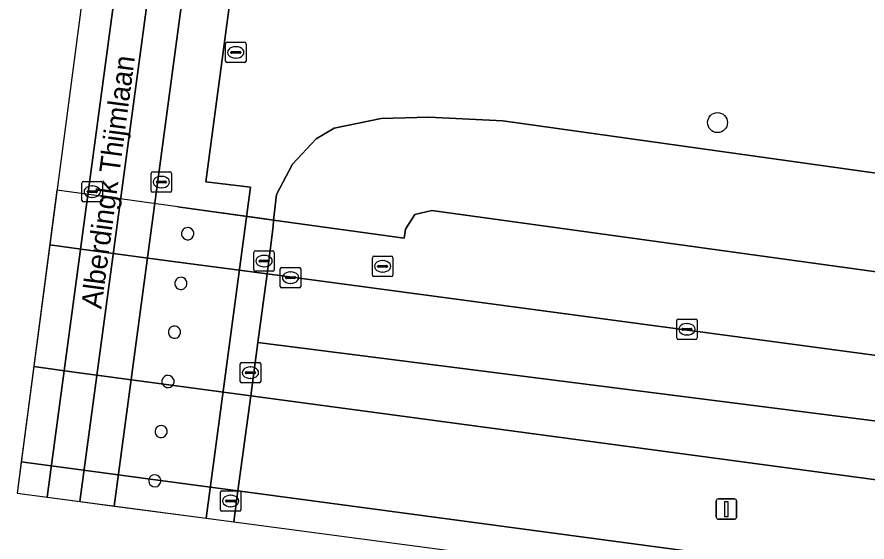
# Model space of a CAD drawing. Extents: x 161402 to 161933, y 381647 to 382315.
# Drawn here: x 161402.16 to 161443.79, y 381705.21 to 381730.95 of the extents above; entities that cross this region are included whole.
import ezdxf

# ---------------------------------------------------------------- set-up
doc = ezdxf.new("R2010")
doc.units = 0
for name, color, linetype in [('IMGEO_Berm_groen', 7, 'Continuous'), ('IMGEO_Boom', 7, 'Continuous'), ('IMGEO_Dek', 7, 'Continuous'), ('IMGEO_Hek', 7, 'Continuous'), ('IMGEO_Kolk', 7, 'Continuous'), ('IMGEO_Lichtmast', 7, 'Continuous'), ('IMGEO_Openbare_ruimte_label', 7, 'Continuous'), ('IMGEO_Pijler', 7, 'Continuous'), ('IMGEO_Rijbaan_lokaal_gesloten', 7, 'Continuous'), ('IMGEO_Rijbaan_lokaal_open', 7, 'Continuous'), ('IMGEO_Rijbaan_regionaal_gesloten', 7, 'Continuous'), ('IMGEO_Rioolput', 7, 'Continuous'), ('IMGEO_Voetpad_open', 7, 'Continuous')]:
    doc.layers.add(name, color=color, linetype=linetype)

msp = doc.modelspace()

# ---------------------------------------------------------------- linework, layer by layer
at = {"layer": 'IMGEO_Berm_groen'}
for points in [[(161414.01, 381742.324), (161413.972, 381742.044), (161413.762, 381740.508), (161411.412, 381722.865), (161413.594, 381722.606), (161411.419, 381706.368), (161412.782, 381706.187)], [(161412.782, 381706.187), (161412.983, 381707.708), (161413.616, 381712.377), (161413.962, 381714.993), (161414.406, 381718.345), (161414.713, 381720.679), (161414.729, 381720.986), (161414.872, 381722.243), (161415.659, 381723.737), (161416.807, 381724.974), (161417.694, 381725.496), (161419.991, 381725.975), (161422.336, 381726.035), (161425.949, 381725.851), (161464.494, 381720.439), (161486.232, 381717.019)], [(161486.232, 381717.019), (161464.494, 381720.439), (161425.949, 381725.851), (161422.336, 381726.035), (161419.991, 381725.975), (161417.694, 381725.496), (161416.807, 381724.974), (161415.659, 381723.737), (161414.872, 381722.243), (161414.729, 381720.986), (161421.115, 381720.1), (161421.193, 381720.541), (161421.637, 381721.268), (161422.47, 381721.45), (161461.503, 381716.064), (161500, 381711.507)], [(161619.348, 381684.737), (161582.68, 381689.648), (161413.616, 381712.377), (161412.983, 381707.708), (161436.501, 381704.561), (161496.223, 381696.587), (161500, 381696.081), (161535.035, 381691.391), (161618.812, 381680.164), (161638.545, 381677.519), (161680.265, 381671.952)]]:
    msp.add_lwpolyline(points, dxfattribs=at)
for points in [[(161403.766, 381719.772), (161405.78, 381719.502), (161409.68, 381718.979), (161414.406, 381718.345), (161414.713, 381720.679), (161414.729, 381720.986), (161414.292, 381721.047), (161410.039, 381721.636), (161406.147, 381722.176), (161404.12, 381722.457)], [(161506.756, 381710.29), (161500, 381711.507), (161461.503, 381716.064), (161422.47, 381721.45), (161421.637, 381721.268), (161421.193, 381720.541), (161421.115, 381720.1), (161414.729, 381720.986), (161414.713, 381720.679), (161414.406, 381718.345), (161620.052, 381690.763), (161588.605, 381697.419), (161577.445, 381699.644), (161568.717, 381701.384), (161533, 381706.394)], [(161402.365, 381709.129), (161404.324, 381708.867), (161408.21, 381708.347), (161412.983, 381707.708), (161413.616, 381712.377), (161408.856, 381713.017), (161404.964, 381713.54), (161402.981, 381713.807)]]:
    msp.add_lwpolyline(points, close=True, dxfattribs=at)
at = {"layer": 'IMGEO_Boom'}
msp.add_circle((161436.469, 381725.768), 0.489, dxfattribs=at)
at = {"layer": 'IMGEO_Dek'}
msp.add_lwpolyline([(161412.782, 381706.187), (161412.983, 381707.708), (161413.616, 381712.377), (161414.406, 381718.345), (161414.713, 381720.679), (161414.729, 381720.986), (161410.039, 381721.636), (161406.147, 381722.176), (161404.12, 381722.457), (161402.163, 381707.599)], close=True, dxfattribs=at)
at = {"layer": 'IMGEO_Hek'}
for points in [[(161406.147, 381722.176), (161404.12, 381722.457)], [(161410.039, 381721.636), (161406.147, 381722.176)], [(161410.039, 381721.636), (161414.729, 381720.986)], [(161421.115, 381720.1), (161414.729, 381720.986)]]:
    msp.add_lwpolyline(points, dxfattribs=at)
at = {"layer": 'IMGEO_Kolk'}
for p, q in [((161412.452, 381729.71), (161413.304, 381729.71)), ((161412.377, 381728.784), (161412.377, 381729.636)), ((161412.679, 381729.253), (161413.077, 381729.253)), ((161412.865, 381729.49), (161412.89, 381729.49)), ((161413.378, 381729.636), (161413.378, 381728.784)), ((161412.636, 381729.204), (161412.636, 381729.216)), ((161413.074, 381729.167), (161412.676, 381729.167)), ((161412.888, 381728.93), (161412.863, 381728.93)), ((161413.12, 381729.216), (161413.12, 381729.204)), ((161413.304, 381728.71), (161412.452, 381728.71)), ((161408.733, 381722.426), (161408.733, 381723.278)), ((161408.808, 381723.352), (161409.66, 381723.352)), ((161409.221, 381723.132), (161409.246, 381723.132)), ((161409.734, 381723.278), (161409.734, 381722.426)), ((161408.992, 381722.846), (161408.992, 381722.858)), ((161409.43, 381722.809), (161409.032, 381722.809)), ((161409.035, 381722.895), (161409.433, 381722.895)), ((161409.476, 381722.858), (161409.476, 381722.846)), ((161409.66, 381722.352), (161408.808, 381722.352)), ((161409.244, 381722.572), (161409.219, 381722.572)), ((161415.058, 381717.74), (161415.058, 381718.592)), ((161415.133, 381718.666), (161415.985, 381718.666)), ((161415.546, 381718.446), (161415.571, 381718.446)), ((161416.059, 381718.592), (161416.059, 381717.74)), ((161415.317, 381718.16), (161415.317, 381718.172)), ((161415.755, 381718.123), (161415.357, 381718.123)), ((161415.36, 381718.209), (161415.758, 381718.209)), ((161415.801, 381718.172), (161415.801, 381718.16)), ((161415.985, 381717.666), (161415.133, 381717.666)), ((161415.569, 381717.886), (161415.544, 381717.886)), ((161434.469, 381715.21), (161434.469, 381716.062)), ((161434.544, 381716.136), (161435.396, 381716.136)), ((161435.47, 381716.062), (161435.47, 381715.21)), ((161434.728, 381715.63), (161434.728, 381715.642)), ((161435.166, 381715.593), (161434.768, 381715.593)), ((161434.771, 381715.679), (161435.169, 381715.679)), ((161434.957, 381715.916), (161434.982, 381715.916)), ((161435.212, 381715.642), (161435.212, 381715.63)), ((161435.396, 381715.136), (161434.544, 381715.136)), ((161434.98, 381715.356), (161434.955, 381715.356))]:
    msp.add_line(p, q, dxfattribs=at)
for points in [[(161412.452, 381729.71), (161413.304, 381729.71)], [(161412.377, 381728.784), (161412.377, 381729.636)], [(161413.378, 381729.636), (161413.378, 381728.784)], [(161413.304, 381728.71), (161412.452, 381728.71)], [(161408.733, 381722.426), (161408.733, 381723.278)], [(161408.808, 381723.352), (161409.66, 381723.352)], [(161409.734, 381723.278), (161409.734, 381722.426)], [(161409.66, 381722.352), (161408.808, 381722.352)], [(161415.058, 381717.74), (161415.058, 381718.592)], [(161415.133, 381718.666), (161415.985, 381718.666)], [(161416.059, 381718.592), (161416.059, 381717.74)], [(161415.985, 381717.666), (161415.133, 381717.666)], [(161434.469, 381715.21), (161434.469, 381716.062)], [(161434.544, 381716.136), (161435.396, 381716.136)], [(161435.47, 381716.062), (161435.47, 381715.21)], [(161435.396, 381715.136), (161434.544, 381715.136)]]:
    msp.add_lwpolyline(points, dxfattribs=at)
for centre, radius, start, end in [((161412.454, 381729.634), 0.0765, 91.552, 178.448), ((161412.454, 381729.634), 0.0765, 91.552, 178.448), ((161413.302, 381729.634), 0.0765, 1.552, 88.448), ((161413.302, 381729.634), 0.0765, 1.552, 88.448), ((161412.676, 381729.213), 0.0403, 85.8775, 175.7526), ((161413.081, 381729.215), 0.0386, 1.7309, 96.639), ((161412.673, 381729.203), 0.0366, 178.938, 274.7102), ((161413.077, 381729.21), 0.043, 264.8664, 352.4533), ((161412.454, 381728.786), 0.0765, 181.552, 268.448), ((161412.454, 381728.786), 0.0765, 181.552, 268.448), ((161413.302, 381728.786), 0.0765, 271.552, 358.448), ((161413.302, 381728.786), 0.0765, 271.552, 358.448), ((161408.81, 381723.276), 0.0765, 91.552, 178.448), ((161408.81, 381723.276), 0.0765, 91.552, 178.448), ((161409.658, 381723.276), 0.0765, 1.552, 88.448), ((161409.658, 381723.276), 0.0765, 1.552, 88.448), ((161409.032, 381722.855), 0.0403, 85.8775, 175.7526), ((161409.029, 381722.845), 0.0366, 178.938, 274.7102), ((161409.433, 381722.852), 0.043, 264.8664, 352.4533), ((161409.437, 381722.857), 0.0386, 1.7309, 96.639), ((161408.81, 381722.428), 0.0765, 181.552, 268.448), ((161408.81, 381722.428), 0.0765, 181.552, 268.448), ((161409.658, 381722.428), 0.0765, 271.552, 358.448), ((161409.658, 381722.428), 0.0765, 271.552, 358.448), ((161415.135, 381718.59), 0.0765, 91.552, 178.448), ((161415.135, 381718.59), 0.0765, 91.552, 178.448), ((161415.983, 381718.59), 0.0765, 1.552, 88.448), ((161415.983, 381718.59), 0.0765, 1.552, 88.448), ((161415.357, 381718.169), 0.0403, 85.8775, 175.7526), ((161415.354, 381718.159), 0.0366, 178.938, 274.7102), ((161415.758, 381718.166), 0.043, 264.8664, 352.4533), ((161415.762, 381718.171), 0.0386, 1.7309, 96.639), ((161415.135, 381717.742), 0.0765, 181.552, 268.448), ((161415.135, 381717.742), 0.0765, 181.552, 268.448), ((161415.983, 381717.742), 0.0765, 271.552, 358.448), ((161415.983, 381717.742), 0.0765, 271.552, 358.448), ((161434.546, 381716.06), 0.0765, 91.552, 178.448), ((161434.546, 381716.06), 0.0765, 91.552, 178.448), ((161435.394, 381716.06), 0.0765, 1.552, 88.448), ((161435.394, 381716.06), 0.0765, 1.552, 88.448), ((161434.768, 381715.639), 0.0403, 85.8775, 175.7526), ((161434.765, 381715.629), 0.0366, 178.938, 274.7102), ((161435.169, 381715.636), 0.043, 264.8664, 352.4533), ((161435.173, 381715.641), 0.0386, 1.7309, 96.639), ((161434.546, 381715.212), 0.0765, 181.552, 268.448), ((161434.546, 381715.212), 0.0765, 181.552, 268.448), ((161435.394, 381715.212), 0.0765, 271.552, 358.448), ((161435.394, 381715.212), 0.0765, 271.552, 358.448)]:
    msp.add_arc(centre, radius, start, end, dxfattribs=at)
for centre, major_axis, ratio, start_param, end_param in [((161412.864, 381729.21), (-0.387, 0.002), 0.722429, 4.712389, 7.853982), ((161412.889, 381729.21), (-0.39, 0.002), 0.717154, 1.570796, 4.712389), ((161409.22, 381722.852), (-0.387, 0.002), 0.722429, 4.712389, 7.853982), ((161409.245, 381722.852), (-0.39, 0.002), 0.717154, 1.570796, 4.712389), ((161415.545, 381718.166), (-0.387, 0.002), 0.722429, 4.712389, 7.853982), ((161415.57, 381718.166), (-0.39, 0.002), 0.717154, 1.570796, 4.712389), ((161434.956, 381715.636), (-0.387, 0.002), 0.722429, 4.712389, 7.853982), ((161434.981, 381715.636), (-0.39, 0.002), 0.717154, 1.570796, 4.712389)]:
    msp.add_ellipse(centre, major_axis=major_axis, ratio=ratio, start_param=start_param, end_param=end_param, dxfattribs=at)
at = {"layer": 'IMGEO_Lichtmast'}
for p, q in [((161436.409, 381706.422), (161436.409, 381707.222)), ((161436.409, 381707.222), (161436.409, 381706.422)), ((161436.509, 381707.322), (161437.299, 381707.322)), ((161437.299, 381707.322), (161436.509, 381707.322)), ((161437.399, 381707.222), (161437.399, 381706.422)), ((161437.399, 381706.422), (161437.399, 381707.222)), ((161437.299, 381706.322), (161436.509, 381706.322)), ((161436.509, 381706.322), (161437.299, 381706.322))]:
    msp.add_line(p, q, dxfattribs=at)
msp.add_lwpolyline([(161436.829, 381707.197), (161436.979, 381707.197), (161436.979, 381706.447), (161436.829, 381706.447), (161436.829, 381707.197)], dxfattribs=at)
for centre, start, end in [((161436.509, 381707.222), 90, 180), ((161436.509, 381707.222), 90, 180), ((161437.299, 381707.222), 0, 90), ((161437.299, 381707.222), 360, 90), ((161436.509, 381706.422), 180, 270), ((161436.509, 381706.422), 180, 270), ((161437.299, 381706.422), 270, 0), ((161437.299, 381706.422), 270, 0)]:
    msp.add_arc(centre, 0.1, start, end, dxfattribs=at)
at = {"layer": 'IMGEO_Pijler'}
for centre, start, end in [((161410.52, 381720.321), 99.5111, 244.796), ((161410.52, 381720.321), 244.9309, 99.3762), ((161410.187, 381717.886), 99.9814, 244.2431), ((161410.188, 381717.886), 244.04, 100.1845), ((161409.873, 381715.491), 103.3562, 240.9652), ((161409.874, 381715.491), 240.8333, 103.4882), ((161409.559, 381713.076), 107.1727, 237.1351), ((161409.559, 381713.076), 237.2026, 107.1053), ((161409.219, 381710.622), 106.9642, 237.3724), ((161409.219, 381710.622), 237.4416, 106.895), ((161408.91, 381708.206), 111.878, 232.4229), ((161408.909, 381708.206), 232.5349, 111.766)]:
    msp.add_arc(centre, 0.299, start, end, dxfattribs=at)
at = {"layer": 'IMGEO_Rijbaan_lokaal_gesloten'}
for points in [[(161403.64, 381707.403), (161408.233, 381741.561), (161406.662, 381741.754), (161402.163, 381707.599)], [(161406.924, 381706.966), (161411.314, 381739.747), (161411.477, 381740.91), (161411.495, 381741.161), (161409.843, 381741.364), (161405.243, 381707.189)]]:
    msp.add_lwpolyline(points, close=True, dxfattribs=at)
at = {"layer": 'IMGEO_Rijbaan_lokaal_open'}
msp.add_lwpolyline([(161405.243, 381707.189), (161409.843, 381741.364), (161408.233, 381741.561), (161403.64, 381707.403)], close=True, dxfattribs=at)
at = {"layer": 'IMGEO_Rijbaan_regionaal_gesloten'}
for points in [[(161402.981, 381713.807), (161404.964, 381713.54), (161408.856, 381713.017), (161413.616, 381712.377), (161413.962, 381714.993), (161414.406, 381718.345), (161409.68, 381718.979), (161405.78, 381719.502), (161403.766, 381719.772)], [(161620.052, 381690.763), (161414.406, 381718.345), (161413.962, 381714.993), (161500.28, 381704.009), (161533.162, 381699.103), (161549.132, 381696.713), (161592.199, 381691.43), (161619.672, 381687.503), (161753.907, 381669.29), (161804.206, 381663.251), (161819.974, 381662.23), (161820.308, 381665.138), (161820.232, 381665.145), (161818.101, 381665.382), (161799.835, 381667.417), (161794.737, 381667.864), (161786.397, 381668.675), (161776.791, 381669.741)], [(161413.962, 381714.993), (161413.616, 381712.377), (161582.68, 381689.648), (161619.348, 381684.737), (161785.447, 381662.49), (161799.427, 381660.835), (161819.493, 381658.805), (161819.974, 381662.23), (161804.206, 381663.251), (161753.907, 381669.29), (161619.672, 381687.503), (161592.199, 381691.43), (161549.132, 381696.713), (161533.162, 381699.103), (161500.28, 381704.009)], [(161412.782, 381706.187), (161412.983, 381707.708), (161408.21, 381708.347), (161404.324, 381708.867), (161402.365, 381709.129), (161402.163, 381707.599)], [(161412.782, 381706.187), (161565.314, 381685.907), (161583.995, 381683.424), (161665.691, 381672.562), (161690.967, 381669.187), (161702.189, 381667.689), (161700.395, 381667.978), (161696.453, 381668.697), (161692.511, 381669.416), (161688.677, 381670.167), (161684.627, 381671.027), (161680.265, 381671.952), (161638.545, 381677.519), (161618.812, 381680.164), (161535.035, 381691.391), (161500, 381696.081), (161496.223, 381696.587), (161436.501, 381704.561), (161412.983, 381707.708)]]:
    msp.add_lwpolyline(points, close=True, dxfattribs=at)
at = {"layer": 'IMGEO_Rioolput'}
for p, q in [((161405.345, 381721.954), (161405.345, 381722.806)), ((161405.42, 381722.88), (161406.272, 381722.88)), ((161405.833, 381722.66), (161405.858, 381722.66)), ((161406.346, 381722.806), (161406.346, 381721.954)), ((161405.604, 381722.374), (161405.604, 381722.386)), ((161406.042, 381722.337), (161405.644, 381722.337)), ((161405.647, 381722.423), (161406.045, 381722.423)), ((161406.088, 381722.386), (161406.088, 381722.374)), ((161406.272, 381721.88), (161405.42, 381721.88)), ((161405.856, 381722.1), (161405.831, 381722.1)), ((161413.762, 381718.554), (161413.762, 381719.406)), ((161413.837, 381719.48), (161414.689, 381719.48)), ((161414.763, 381719.406), (161414.763, 381718.554)), ((161414.021, 381718.974), (161414.021, 381718.986)), ((161414.459, 381718.937), (161414.061, 381718.937)), ((161414.064, 381719.023), (161414.462, 381719.023)), ((161414.25, 381719.26), (161414.275, 381719.26)), ((161414.505, 381718.986), (161414.505, 381718.974)), ((161419.566, 381718.293), (161419.566, 381719.145)), ((161419.641, 381719.219), (161420.493, 381719.219)), ((161420.054, 381718.999), (161420.079, 381718.999)), ((161420.567, 381719.145), (161420.567, 381718.293)), ((161414.689, 381718.48), (161413.837, 381718.48)), ((161414.273, 381718.7), (161414.248, 381718.7)), ((161419.825, 381718.713), (161419.825, 381718.725)), ((161420.263, 381718.676), (161419.865, 381718.676)), ((161419.868, 381718.762), (161420.266, 381718.762)), ((161420.077, 381718.439), (161420.052, 381718.439)), ((161420.309, 381718.725), (161420.309, 381718.713)), ((161420.493, 381718.219), (161419.641, 381718.219)), ((161413.095, 381713.082), (161413.095, 381713.934)), ((161413.17, 381714.008), (161414.022, 381714.008)), ((161414.096, 381713.934), (161414.096, 381713.082)), ((161413.354, 381713.502), (161413.354, 381713.514)), ((161413.792, 381713.465), (161413.394, 381713.465)), ((161413.397, 381713.551), (161413.795, 381713.551)), ((161413.583, 381713.788), (161413.608, 381713.788)), ((161413.838, 381713.514), (161413.838, 381713.502)), ((161413.606, 381713.228), (161413.581, 381713.228)), ((161414.022, 381713.008), (161413.17, 381713.008)), ((161412.124, 381706.791), (161412.124, 381707.643)), ((161412.199, 381707.717), (161413.051, 381707.717)), ((161413.125, 381707.643), (161413.125, 381706.791)), ((161412.383, 381707.211), (161412.383, 381707.223)), ((161412.426, 381707.26), (161412.824, 381707.26)), ((161412.612, 381707.497), (161412.637, 381707.497)), ((161412.867, 381707.223), (161412.867, 381707.211)), ((161412.821, 381707.174), (161412.423, 381707.174)), ((161412.635, 381706.937), (161412.61, 381706.937)), ((161413.051, 381706.717), (161412.199, 381706.717))]:
    msp.add_line(p, q, dxfattribs=at)
for points in [[(161405.345, 381721.954), (161405.345, 381722.806)], [(161405.42, 381722.88), (161406.272, 381722.88)], [(161406.346, 381722.806), (161406.346, 381721.954)], [(161406.272, 381721.88), (161405.42, 381721.88)], [(161413.762, 381718.554), (161413.762, 381719.406)], [(161413.837, 381719.48), (161414.689, 381719.48)], [(161414.763, 381719.406), (161414.763, 381718.554)], [(161419.566, 381718.293), (161419.566, 381719.145)], [(161419.641, 381719.219), (161420.493, 381719.219)], [(161420.567, 381719.145), (161420.567, 381718.293)], [(161414.689, 381718.48), (161413.837, 381718.48)], [(161420.493, 381718.219), (161419.641, 381718.219)], [(161413.095, 381713.082), (161413.095, 381713.934)], [(161413.17, 381714.008), (161414.022, 381714.008)], [(161414.096, 381713.934), (161414.096, 381713.082)], [(161414.022, 381713.008), (161413.17, 381713.008)], [(161412.124, 381706.791), (161412.124, 381707.643)], [(161412.199, 381707.717), (161413.051, 381707.717)], [(161413.125, 381707.643), (161413.125, 381706.791)], [(161413.051, 381706.717), (161412.199, 381706.717)]]:
    msp.add_lwpolyline(points, dxfattribs=at)
for centre, radius, start, end in [((161405.422, 381722.804), 0.0765, 91.552, 178.448), ((161405.422, 381722.804), 0.0765, 91.552, 178.448), ((161406.27, 381722.804), 0.0765, 1.552, 88.448), ((161406.27, 381722.804), 0.0765, 1.552, 88.448), ((161405.644, 381722.383), 0.0403, 85.8775, 175.7526), ((161405.641, 381722.373), 0.0366, 178.938, 274.7102), ((161406.045, 381722.38), 0.043, 264.8664, 352.4533), ((161406.049, 381722.385), 0.0386, 1.7309, 96.639), ((161405.422, 381721.956), 0.0765, 181.552, 268.448), ((161405.422, 381721.956), 0.0765, 181.552, 268.448), ((161406.27, 381721.956), 0.0765, 271.552, 358.448), ((161406.27, 381721.956), 0.0765, 271.552, 358.448), ((161413.839, 381719.404), 0.0765, 91.552, 178.448), ((161413.839, 381719.404), 0.0765, 91.552, 178.448), ((161414.687, 381719.404), 0.0765, 1.552, 88.448), ((161414.687, 381719.404), 0.0765, 1.552, 88.448), ((161414.061, 381718.983), 0.0403, 85.8775, 175.7526), ((161414.058, 381718.973), 0.0366, 178.938, 274.7102), ((161414.462, 381718.98), 0.043, 264.8664, 352.4533), ((161414.466, 381718.985), 0.0386, 1.7309, 96.639), ((161419.643, 381719.143), 0.0765, 91.552, 178.448), ((161419.643, 381719.143), 0.0765, 91.552, 178.448), ((161420.491, 381719.143), 0.0765, 1.552, 88.448), ((161420.491, 381719.143), 0.0765, 1.552, 88.448), ((161413.839, 381718.556), 0.0765, 181.552, 268.448), ((161413.839, 381718.556), 0.0765, 181.552, 268.448), ((161414.687, 381718.556), 0.0765, 271.552, 358.448), ((161414.687, 381718.556), 0.0765, 271.552, 358.448), ((161419.865, 381718.722), 0.0403, 85.8775, 175.7526), ((161419.862, 381718.712), 0.0366, 178.938, 274.7102), ((161420.266, 381718.719), 0.043, 264.8664, 352.4533), ((161420.27, 381718.724), 0.0386, 1.7309, 96.639), ((161419.643, 381718.295), 0.0765, 181.552, 268.448), ((161419.643, 381718.295), 0.0765, 181.552, 268.448), ((161420.491, 381718.295), 0.0765, 271.552, 358.448), ((161420.491, 381718.295), 0.0765, 271.552, 358.448), ((161413.172, 381713.932), 0.0765, 91.552, 178.448), ((161413.172, 381713.932), 0.0765, 91.552, 178.448), ((161414.02, 381713.932), 0.0765, 1.552, 88.448), ((161414.02, 381713.932), 0.0765, 1.552, 88.448), ((161413.394, 381713.511), 0.0403, 85.8775, 175.7526), ((161413.391, 381713.501), 0.0366, 178.938, 274.7102), ((161413.795, 381713.508), 0.043, 264.8664, 352.4533), ((161413.799, 381713.513), 0.0386, 1.7309, 96.639), ((161413.172, 381713.084), 0.0765, 181.552, 268.448), ((161413.172, 381713.084), 0.0765, 181.552, 268.448), ((161414.02, 381713.084), 0.0765, 271.552, 358.448), ((161414.02, 381713.084), 0.0765, 271.552, 358.448), ((161412.201, 381707.641), 0.0765, 91.552, 178.448), ((161412.201, 381707.641), 0.0765, 91.552, 178.448), ((161413.049, 381707.641), 0.0765, 1.552, 88.448), ((161413.049, 381707.641), 0.0765, 1.552, 88.448), ((161412.423, 381707.22), 0.0403, 85.8775, 175.7526), ((161412.42, 381707.21), 0.0366, 178.938, 274.7102), ((161412.824, 381707.217), 0.043, 264.8664, 352.4533), ((161412.828, 381707.222), 0.0386, 1.7309, 96.639), ((161412.201, 381706.793), 0.0765, 181.552, 268.448), ((161412.201, 381706.793), 0.0765, 181.552, 268.448), ((161413.049, 381706.793), 0.0765, 271.552, 358.448), ((161413.049, 381706.793), 0.0765, 271.552, 358.448)]:
    msp.add_arc(centre, radius, start, end, dxfattribs=at)
for centre, major_axis, ratio, start_param, end_param in [((161405.832, 381722.38), (-0.387, 0.002), 0.722429, 4.712389, 7.853982), ((161405.857, 381722.38), (-0.39, 0.002), 0.717154, 1.570796, 4.712389), ((161414.249, 381718.98), (-0.387, 0.002), 0.722429, 4.712389, 7.853982), ((161414.274, 381718.98), (-0.39, 0.002), 0.717154, 1.570796, 4.712389), ((161420.053, 381718.719), (-0.387, 0.002), 0.722429, 4.712389, 7.853982), ((161420.078, 381718.719), (-0.39, 0.002), 0.717154, 1.570796, 4.712389), ((161413.582, 381713.508), (-0.387, 0.002), 0.722429, 4.712389, 7.853982), ((161413.607, 381713.508), (-0.39, 0.002), 0.717154, 1.570796, 4.712389), ((161412.611, 381707.217), (-0.387, 0.002), 0.722429, 4.712389, 7.853982), ((161412.636, 381707.217), (-0.39, 0.002), 0.717154, 1.570796, 4.712389)]:
    msp.add_ellipse(centre, major_axis=major_axis, ratio=ratio, start_param=start_param, end_param=end_param, dxfattribs=at)
at = {"layer": 'IMGEO_Voetpad_open'}
for points in [[(161411.629, 381743.147), (161411.533, 381741.683), (161411.495, 381741.161), (161411.477, 381740.91), (161411.314, 381739.747), (161406.924, 381706.966)], [(161406.924, 381706.966), (161411.419, 381706.368), (161413.594, 381722.606), (161411.412, 381722.865), (161413.762, 381740.508), (161413.972, 381742.044), (161414.01, 381742.324)]]:
    msp.add_lwpolyline(points, dxfattribs=at)
for centre, start, end in [((161410.52, 381720.321), 99.5111, 244.796), ((161410.52, 381720.321), 244.9309, 99.3762), ((161410.187, 381717.886), 99.9814, 244.2431), ((161410.188, 381717.886), 244.04, 100.1845), ((161409.873, 381715.491), 103.3562, 240.9652), ((161409.874, 381715.491), 240.8333, 103.4882), ((161409.559, 381713.076), 107.1727, 237.1351), ((161409.559, 381713.076), 237.2026, 107.1053), ((161409.219, 381710.622), 106.9642, 237.3724), ((161409.219, 381710.622), 237.4416, 106.895), ((161408.91, 381708.206), 111.878, 232.4229), ((161408.909, 381708.206), 232.5349, 111.766)]:
    msp.add_arc(centre, 0.299, start, end, dxfattribs=at)

# ---------------------------------------------------------------- texts
at = {"layer": 'IMGEO_Openbare_ruimte_label'}
msp.add_text('Alberdingk Thijmlaan', height=1, rotation=82.4129, dxfattribs=at).set_placement((161406.293, 381716.604))

doc.saveas('drawing.dxf')
